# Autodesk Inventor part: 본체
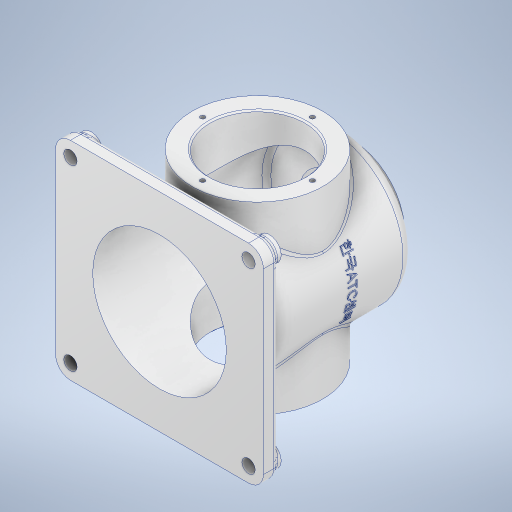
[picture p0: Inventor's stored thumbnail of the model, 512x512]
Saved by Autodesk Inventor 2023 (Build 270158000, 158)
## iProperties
Created: 2025-05
Part Number: 본체
Material: 알루미늄 6061
Document SubType Name: Modeling
Designer: ADMIN_PC
Density: 2.7 g/cm^3
Appearance: 알루미늄 - 평지
Mass: 1269.01 g
Surface Area: 1198.64 cm^2
Volume: 470.004 cm^3
Author: ADMIN_PC
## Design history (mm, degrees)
sketch "스케치1"
  geometry: C1 r 50 at (0, 0); 1 further point
  constraints: 1 centre point, 1 coincident
  dimensions: "d0" = 100 diameter of C1
extrude "돌출1" new body sketch "스케치1" stored distance "d1" = 112; taper "d2" = 0 deg
sketch "스케치2"
  geometry: L1 (-70, -70)-(70, -70); L2 (70, -70)-(70, 70); L3 (70, 70)-(-70, 70); L4 (-70, 70)-(-70, -70); L5 (-70, -70)-(70, 70); L6 (70, -70)-(-70, 70); 1 further point
  constraints: 12 end point, 2 midpoint, 2 parallel, 1 horizontal, 1 perpendicular
  dimensions: "d3" = 140 distance of L2.end L3.end; "d4" = 140 distance of L1.end L2.end
extrude "돌출2" join sketch "스케치2" distance "d5" = 10; taper "d6" = 0 deg
sketch "스케치3"
  geometry: C1 r 35 at (0, 0); 1 further point
  constraints: 1 centre point, 1 coincident
  dimensions: "d7" = 70 diameter of C1
extrude "돌출3" join sketch "스케치3" distance "d8" = 8; taper "d9" = 0 deg
node "작업 평면1"
sketch "스케치4"
  geometry: C1 r 44 at (0, 0); 1 further point
  constraints: 1 centre point, 1 coincident
  dimensions: "d11" = 88 diameter of C1
extrude "돌출4" join sketch "스케치4" stored distance "d12" = 8; taper "d13" = 0 deg
sketch "스케치5"
  geometry: C1 r 23 at (0, 0); 1 further point
  constraints: 1 centre point, 1 coincident
  dimensions: "d14" = 46 diameter of C1
extrude "돌출5" cut sketch "스케치5" extent not by distance; stored distance "d15" = 0; taper "d16" = 0 deg
sketch "스케치6"
  geometry: C1 r 45 at (0, 0); 1 further point
  constraints: 1 centre point, 1 coincident
  dimensions: "d17" = 90 diameter of C1
extrude "돌출6" cut sketch "스케치6" distance "d18" = 117; taper "d19" = 0 deg
sketch "스케치7"
  geometry: C1 r 32 at (0, 0); 1 further point
  constraints: 1 centre point, 1 coincident
  dimensions: "d20" = 64 diameter of C1
extrude "돌출7" cut sketch "스케치7" extent not by distance; stored distance "d21" = 0; taper "d22" = 0 deg
sketch "스케치8"
  geometry: L1 (-60, -60)-(60, -60); L2 (60, -60)-(60, 60); L3 (60, 60)-(-60, 60); L4 (-60, 60)-(-60, -60); L5 (-60, -60)-(60, 60); L6 (60, -60)-(-60, 60); C1 r 8 at (60, 60); C2 r 8 at (60, -60); 1 further point
  constraints: 12 end point, 2 centre point, 2 coincident, 2 midpoint, 2 parallel, 1 horizontal, 1 perpendicular
  dimensions: "d23" = 120 distance of L2.end L3.end; "d24" = 120 distance of L1.end L2.end; "d25" = 16 diameter of C1; "d26" = 16 diameter of C2
extrude "돌출8" join sketch "스케치8" distance "d27" = 4; taper "d28" = 0 deg
sketch "스케치9"
  geometry: L1 (10, 130)-(10, -10) reference; L2 (10, -10)-(-130, -10) reference; L3 (38, 60)-(-158, 60) reference; C1 r 4.5 at (0, 0); C2 r 4.5 at (0, 120); 1 further point
  constraints: 2 centre point, 1 symmetric about line, 1 other
  dimensions: "d29" = 9 diameter of C1; "d30" = 10 distance from line of L1 C1.centre; "d31" = 10 distance from line of L2 C1.centre
extrude "돌출9" cut sketch "스케치9" extent not by distance; stored distance "d32" = 0; taper "d33" = 0 deg
sketch "스케치10" dims "d68" = 74
  geometry: L1 (0, -90)-(0, 92) reference; L2 (-70, 66)-(70, 66) reference; 2 further points
  constraints: 1 point on line, 1 vertical alignment, 2 other
hole "구멍1" sketch "스케치10" at (0, -37) diameter "d35" = 3.242; stored, may be unused: countersink angle "d39" = 90 deg, drill point angle "d41" = 118 deg; dims "d36" = 8, "d37" = 4, "d38" = 2, "d40" = 10
sketch "스케치11" dims "d45" = 56
  geometry: L1 (0, -98)-(0, 98) reference; 3 further points
  constraints: 1 coincident, 1 point on line, 1 vertical alignment, 2 other
hole "구멍2" sketch "스케치11" at (0, -28) diameter "d46" = 3.242; stored, may be unused: countersink angle "d50" = 90 deg, drill point angle "d52" = 118 deg; dims "d47" = 8, "d48" = 4, "d49" = 2, "d51" = 10
node "작업 평면2"
sketch "스케치12"
  geometry: L1 (-70, 66)-(70, 66) reference; L2 (-62, -44)-(-62, 44) reference; 2 further points
  constraints: 1 other
  dimensions: "d57" = 80 distance from line of L1 point (0, -14); "d58" = 62 distance from line of L2 point (0, -14)
feature "엠보싱1" sketch "스케치12" dims "d2" = 0, "d11" = 88, "d59" = 0.5, "d60" = 0
fillet "모깎기1" dims "d61" = 10
fillet "모깎기2" dims "d62" = 3
fillet "모깎기3" dims "d63" = 3
chamfer "모따기1" distance "d64" = 1; stored, may be unused: second distance "d65" = 2, angle "d66" = 45 deg
fillet "모깎기4" dims "d67" = 8
node "솔리드1"
mirror "미러1"
mirror "미러2"
mirror "미러3"
pattern_circular "원형 패턴1" dims angle "d43" = 360 deg
mirror "미러4"
pattern_circular "원형 패턴2" dims angle "d54" = 360 deg
feature "A9D066F2-1C7D-4E18-AEED-F7BC21143FA4" dims "d35" = 3.242, "d36" = 8, "d37" = 4, "d38" = 2, "d39" = 90 deg, "d40" = 10, "d41" = 118 deg
other parameters: "d10" = 62
